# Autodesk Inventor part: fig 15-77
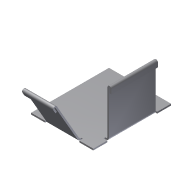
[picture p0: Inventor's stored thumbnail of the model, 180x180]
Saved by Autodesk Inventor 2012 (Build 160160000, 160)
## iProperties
Shininess: 77.0
Angle Display Precision: 2
Document Length Units: 11269
Document Angle Units: 11279
Document Time Units: 11290
Document Mass Units: 11283
Document Length Units Precision: 3
Document Angle Units Precision: 2
Compacted: True
Created: 2002-04
Part Number: fig 15-77
Document SubType Name: Sheet Metal
Density: 1 g/cm^3
Sheet Metal Rule: Default
Material: Default
Density: 0.0
Volumn: 0.0
Area: 0.0
PropertySet Name: Model Information
Control State: 0
Master: False
Checked Out: False
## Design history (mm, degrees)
node "Face1"
  sketch "Sketch1"
    geometry: L1 (-17.882, 11.882)-(2.118, 11.882); L2 (2.118, 11.882)-(2.118, -13.176); L3 (2.118, -13.176)-(-17.882, -13.176); L4 (-17.882, -13.176)-(-17.882, 11.882)
    constraints: 8 end point, 2 parallel, 1 horizontal, 1 perpendicular
    dimensions: "d17" = 20 distance of L2.end L3.end
node "Flange2"
node "Flange3"
feature "Hem8" dims "d82" = 0.5 (= BendReliefWidth), "d83" = 0.25 (= BendReliefDepth), "d84" = 1 (= MinimumRemnant), "d85" = 0.5 (= BendRadius), "d86" = 2 (= 4 x Thickness), "d87" = 0.25 (= 0.5 x Thickness), "d88" = 0.125 (= 0.5 x d87), "SeamGap" = 0.01, "Thickness" = 0.5
feature "Hem9" dims "d89" = 0.5 (= BendReliefWidth), "d90" = 0.25 (= BendReliefDepth), "d91" = 1 (= MinimumRemnant), "d92" = 0.5 (= BendRadius), "d93" = 2 (= 4 x Thickness), "d94" = 0.25 (= 0.5 x Thickness), "d95" = 0.125 (= 0.5 x d94), "SeamGap" = 0.01, "Thickness" = 0.5
body "Solid1"
face "Plate1" dims "Thickness" = 0.5
sketch "Sketch3"
  geometry: L1 (5, 0)-(20, 0); L2 (20, 0)-(20, 15); L3 (20, 15)-(5, 15); L4 (5, 15)-(5, 0)
  constraints: 8 end point
face "Plate3" dims "d6" = 15, "d7" = 90 deg, "d8" = 0.5 (= BendRadius), "d18" = 5, "d19" = 15, "Thickness" = 0.5, "MinimumRemnant" = 1 (= 2 x Thickness), "BendReliefWidth" = 0.5 (= Thickness)
bend "Bend2" dims "d6" = 15, "d7" = 90 deg, "d8" = 0.5 (= BendRadius), "d56" = 0.5 (= BendReliefWidth), "d57" = 0.25 (= BendReliefDepth), "d58" = 1 (= MinimumRemnant), "SeamGap" = 0.01, "Thickness" = 0.5, "MinimumRemnant" = 1 (= 2 x Thickness), "BendReliefWidth" = 0.5 (= Thickness), "TransitionRadius" = 0.5 (= BendRadius)
sketch "Sketch6"
  geometry: L1 (15, 0)-(5, 0); L2 (5, 0)-(5, 15); L3 (5, 15)-(15, 15); L4 (15, 15)-(15, 0)
  constraints: 8 end point
face "Plate4" dims "d20" = 5, "d21" = 10, "d23" = 15, "d24" = 60 deg, "d25" = 0.5 (= BendRadius), "Thickness" = 0.5, "MinimumRemnant" = 1 (= 2 x Thickness), "BendReliefWidth" = 0.5 (= Thickness)
bend "Bend3" dims "d22" = 0.5 (= BendRadius), "d23" = 15, "d24" = 60 deg, "d25" = 0.5 (= BendRadius), "d59" = 0.5 (= BendReliefWidth), "d60" = 0.25 (= BendReliefDepth), "d61" = 1 (= MinimumRemnant), "SeamGap" = 0.01, "Thickness" = 0.5, "MinimumRemnant" = 1 (= 2 x Thickness), "BendReliefWidth" = 0.5 (= Thickness)
sketch "Sketch12"
  geometry: L1 (0.433, 0.25)-(0, 0); L2 (-0.217, -0.125)-(0.471, -1.316); L3 (0.471, -1.316)-(0.038, -1.566); L4 (0.038, -1.566)-(-0.65, -0.375); A1 r 0.125 centre (-0.108, -0.063) between (0, 0) and (-0.217, -0.125); A2 r 0.625 centre (-0.108, -0.063) between (0.433, 0.25) and (-0.65, -0.375)
  constraints: 8 end point, 4 point on circle
sketch "Sketch13"
  geometry: L1 (0.5, 0)-(0, 0); L2 (-0.25, 0)-(-0.25, -1.375); L3 (-0.25, -1.375)-(-0.75, -1.375); L4 (-0.75, -1.375)-(-0.75, 0); A1 r 0.125 centre (-0.125, 0) between (0, 0) and (-0.25, 0); A2 r 0.625 centre (-0.125, 0) between (0.5, 0) and (-0.75, 0)
  constraints: 8 end point, 4 point on circle
other parameters: "BendRadius" = 0.5 (= Thickness), "BendReliefDepth" = 0.25 (= 0.5 x Thickness), "CornerReliefSize" = 2 (= 4 x Thickness), "d0" = 0.5 (= BendRadius), "d5" = 0.5 (= BendRadius), "d26" = 0.5 (= BendRadius), "d30" = 0.5 (= BendRadius), "JacobiRadiusSize" = 0.5 (= Thickness), "GapSize" = 0.5 (= Thickness)
